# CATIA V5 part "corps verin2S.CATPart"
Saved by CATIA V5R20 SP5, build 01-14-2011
Part number: corps verin2S
Publications: "Plan.1"
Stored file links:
  U:\think motion\fin\corps verin2S.CATPart
  U:\think motion\fin\squelette.CATProduct
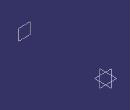
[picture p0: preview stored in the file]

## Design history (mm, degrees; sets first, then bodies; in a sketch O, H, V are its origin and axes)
External parameters (linked from other documents)
  `External.implentation verin2` = 130 mm
Set1
  Plane1: type Offset, RefPlane zx-plane, Offset 205 {= `External.implentation verin2` +75mm}, reversed
Body1 (main body)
